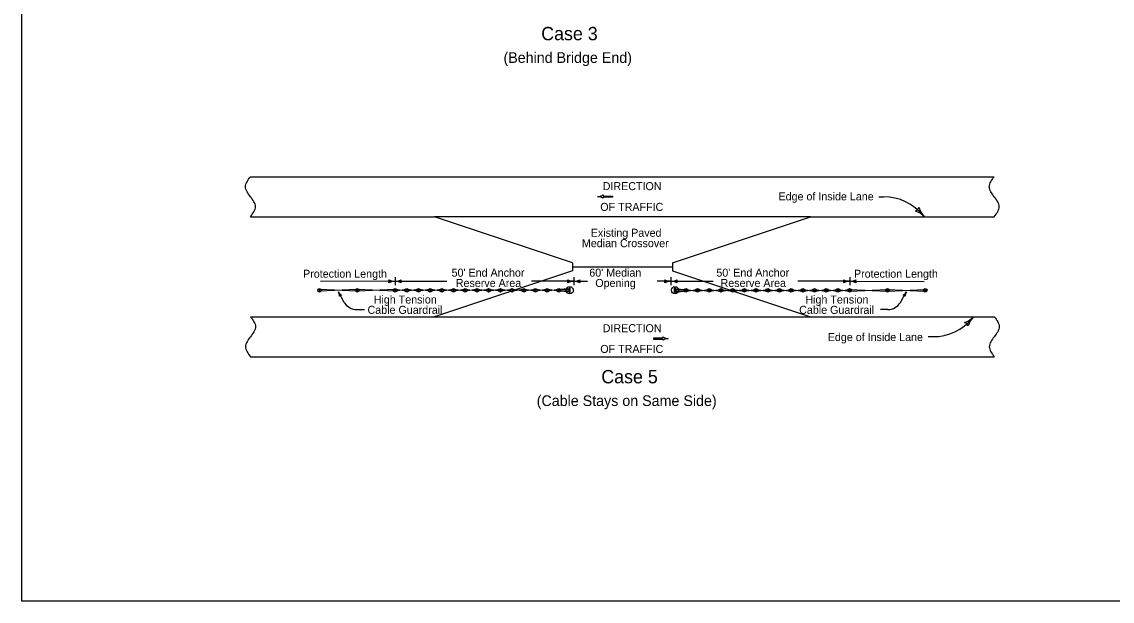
# Model space of a CAD drawing. Extents: x 10133 to 81668, y 7924 to 11018.
# Drawn here: x 20933 to 22568, y 7924 to 8793 of the extents above; entities that cross this region are included whole.
import ezdxf

# ---------------------------------------------------------------- set-up
doc = ezdxf.new("R2010")
doc.units = 0
for name, color, linetype in [('dsnCellElements', 7, 'Continuous'), ('DsnShtRevisedText', 7, 'Continuous'), ('dsnStdDimension', 7, 'Continuous'), ('Level 8', 7, 'Continuous'), ('SheetBorder', 7, 'Continuous')]:
    doc.layers.add(name, color=color, linetype=linetype)

msp = doc.modelspace()

# ---------------------------------------------------------------- linework, layer by layer
at = {"layer": 'dsnCellElements'}
for p, q in [((21758.3, 8425.6), (21908.3, 8425.6)), ((21435.2, 8391.3), (21379.4, 8389)), ((21435.2, 8389), (21379.4, 8391.3)), ((21491.9, 8391.3), (21436.1, 8389)), ((21491.9, 8389), (21436.1, 8391.3)), ((21509.5, 8391.3), (21492.8, 8389)), ((21509.5, 8389), (21492.8, 8391.3)), ((21527, 8391.3), (21510.4, 8389)), ((21527, 8389), (21510.4, 8391.3)), ((21544.6, 8391.3), (21527.9, 8389)), ((21544.6, 8389), (21527.9, 8391.3)), ((21562.1, 8391.3), (21545.5, 8389)), ((21562.1, 8389), (21545.5, 8391.3)), ((21579.6, 8391.3), (21563, 8389)), ((21579.6, 8389), (21563, 8391.3)), ((21597.2, 8391.3), (21580.6, 8389)), ((21597.2, 8389), (21580.6, 8391.3)), ((21614.7, 8391.3), (21598.1, 8389)), ((21614.7, 8389), (21598.1, 8391.3)), ((21632.3, 8389), (21615.7, 8391.3)), ((21632.3, 8391.3), (21615.7, 8389)), ((21649.8, 8391.3), (21633.2, 8389)), ((21649.8, 8389), (21633.2, 8391.3)), ((21667.3, 8391.3), (21650.8, 8389)), ((21667.3, 8389), (21650.8, 8391.3)), ((21684.9, 8391.3), (21668.3, 8389)), ((21684.9, 8389), (21668.3, 8391.3)), ((21702.4, 8391.3), (21685.9, 8389)), ((21702.4, 8389), (21685.9, 8391.3)), ((21720, 8391.3), (21703.4, 8389)), ((21720, 8389), (21703.4, 8391.3)), ((21737.5, 8391.3), (21721, 8389)), ((21737.5, 8389), (21721, 8391.3)), ((21754.3, 8392.5), (21737.5, 8391.3)), ((21754.3, 8391.3), (21738.5, 8391.3)), ((21912.3, 8392.5), (21929, 8391.3)), ((21912.3, 8391.3), (21928.1, 8391.3)), ((21929, 8391.3), (21945.6, 8389)), ((21929, 8389), (21945.6, 8391.3)), ((21946.5, 8391.3), (21963.2, 8389)), ((21946.5, 8389), (21963.2, 8391.3)), ((21964.1, 8391.3), (21980.7, 8389)), ((21964.1, 8389), (21980.7, 8391.3)), ((21981.6, 8391.3), (21998.3, 8389)), ((21981.6, 8389), (21998.3, 8391.3)), ((21999.2, 8391.3), (22015.8, 8389)), ((21999.2, 8389), (22015.8, 8391.3)), ((22016.7, 8391.3), (22033.4, 8389)), ((22016.7, 8389), (22033.4, 8391.3)), ((22034.3, 8389), (22050.9, 8391.3)), ((22034.3, 8391.3), (22050.9, 8389)), ((22051.8, 8391.3), (22068.5, 8389)), ((22051.8, 8389), (22068.5, 8391.3)), ((22069.4, 8391.3), (22086, 8389)), ((22069.4, 8389), (22086, 8391.3)), ((22086.9, 8391.3), (22103.6, 8389)), ((22086.9, 8389), (22103.6, 8391.3)), ((22104.5, 8391.3), (22121.1, 8389)), ((22104.5, 8389), (22121.1, 8391.3)), ((22122, 8391.3), (22138.6, 8389)), ((22122, 8389), (22138.6, 8391.3)), ((22139.6, 8391.3), (22156.2, 8389)), ((22139.6, 8389), (22156.2, 8391.3)), ((22157.1, 8391.3), (22173.7, 8389)), ((22157.1, 8389), (22173.7, 8391.3)), ((22174.7, 8391.3), (22230.4, 8389)), ((22174.7, 8389), (22230.4, 8391.3)), ((22231.4, 8391.3), (22287.1, 8389)), ((22231.4, 8389), (22287.1, 8391.3)), ((21754.3, 8387.8), (21737.5, 8389)), ((21754.3, 8389), (21738.5, 8389)), ((21912.3, 8389), (21928.1, 8389)), ((21912.3, 8387.8), (21929, 8389))]:
    msp.add_line(p, q, dxfattribs=at)
for points in [[(21379.4, 8389), (21379.4, 8391.3), (21378.5, 8391.3), (21378.5, 8389)], [(21436.1, 8389), (21436.1, 8391.3), (21435.2, 8391.3), (21435.2, 8389)], [(21436.1, 8389), (21436.1, 8391.3), (21435.2, 8391.3), (21435.2, 8389)], [(21492.8, 8389), (21492.8, 8391.3), (21491.9, 8391.3), (21491.9, 8389)], [(21492.8, 8389), (21492.8, 8391.3), (21491.9, 8391.3), (21491.9, 8389)], [(21510.4, 8389), (21510.4, 8391.3), (21509.5, 8391.3), (21509.5, 8389)], [(21527.9, 8389), (21527.9, 8391.3), (21527, 8391.3), (21527, 8389)], [(21545.5, 8389), (21545.5, 8391.3), (21544.6, 8391.3), (21544.6, 8389)], [(21563, 8389), (21563, 8391.3), (21562.1, 8391.3), (21562.1, 8389)], [(21580.6, 8389), (21580.6, 8391.3), (21579.6, 8391.3), (21579.6, 8389)], [(21598.1, 8389), (21598.1, 8391.3), (21597.2, 8391.3), (21597.2, 8389)], [(21615.7, 8389), (21615.7, 8391.3), (21614.7, 8391.3), (21614.7, 8389)], [(21633.2, 8389), (21633.2, 8391.3), (21632.3, 8391.3), (21632.3, 8389)], [(21650.8, 8389), (21650.8, 8391.3), (21649.8, 8391.3), (21649.8, 8389)], [(21668.3, 8389), (21668.3, 8391.3), (21667.3, 8391.3), (21667.3, 8389)], [(21685.9, 8389), (21685.9, 8391.3), (21684.9, 8391.3), (21684.9, 8389)], [(21703.4, 8389), (21703.4, 8391.3), (21702.4, 8391.3), (21702.4, 8389)], [(21721, 8389), (21721, 8391.3), (21720, 8391.3), (21720, 8389)], [(21738.5, 8389), (21738.5, 8391.3), (21737.5, 8391.3), (21737.5, 8389)], [(21754.9, 8387.1), (21754.9, 8393.2), (21753.7, 8393.2), (21753.7, 8387.1)], [(21911.7, 8387.1), (21911.7, 8393.2), (21912.9, 8393.2), (21912.9, 8387.1)], [(21928.1, 8389), (21928.1, 8391.3), (21929, 8391.3), (21929, 8389)], [(21945.6, 8389), (21945.6, 8391.3), (21946.5, 8391.3), (21946.5, 8389)], [(21963.2, 8389), (21963.2, 8391.3), (21964.1, 8391.3), (21964.1, 8389)], [(21980.7, 8389), (21980.7, 8391.3), (21981.6, 8391.3), (21981.6, 8389)], [(21998.3, 8389), (21998.3, 8391.3), (21999.2, 8391.3), (21999.2, 8389)], [(22015.8, 8389), (22015.8, 8391.3), (22016.7, 8391.3), (22016.7, 8389)], [(22033.4, 8389), (22033.4, 8391.3), (22034.3, 8391.3), (22034.3, 8389)], [(22050.9, 8389), (22050.9, 8391.3), (22051.8, 8391.3), (22051.8, 8389)], [(22068.5, 8389), (22068.5, 8391.3), (22069.4, 8391.3), (22069.4, 8389)], [(22086, 8389), (22086, 8391.3), (22086.9, 8391.3), (22086.9, 8389)], [(22103.6, 8389), (22103.6, 8391.3), (22104.5, 8391.3), (22104.5, 8389)], [(22121.1, 8389), (22121.1, 8391.3), (22122, 8391.3), (22122, 8389)], [(22138.6, 8389), (22138.6, 8391.3), (22139.6, 8391.3), (22139.6, 8389)], [(22156.2, 8389), (22156.2, 8391.3), (22157.1, 8391.3), (22157.1, 8389)], [(22173.7, 8389), (22173.7, 8391.3), (22174.7, 8391.3), (22174.7, 8389)], [(22173.7, 8389), (22173.7, 8391.3), (22174.7, 8391.3), (22174.7, 8389)], [(22230.4, 8389), (22230.4, 8391.3), (22231.4, 8391.3), (22231.4, 8389)], [(22230.4, 8389), (22230.4, 8391.3), (22231.4, 8391.3), (22231.4, 8389)], [(22287.1, 8389), (22287.1, 8391.3), (22288.1, 8391.3), (22288.1, 8389)]]:
    msp.add_lwpolyline(points, close=True, dxfattribs=at)
for centre, radius in [((21379, 8390.2), 2.66), ((21435.7, 8390.2), 2.66), ((21435.7, 8390.2), 2.66), ((21492.4, 8390.2), 2.66), ((21492.4, 8390.2), 2.66), ((21509.9, 8390.2), 2.66), ((21527.5, 8390.2), 2.66), ((21545, 8390.2), 2.66), ((21562.5, 8390.2), 2.66), ((21580.1, 8390.2), 2.66), ((21597.6, 8390.2), 2.66), ((21615.2, 8390.2), 2.66), ((21632.7, 8390.2), 2.66), ((21650.3, 8390.2), 2.66), ((21667.8, 8390.2), 2.66), ((21685.4, 8390.2), 2.66), ((21702.9, 8390.2), 2.66), ((21720.5, 8390.2), 2.66), ((21738, 8390.2), 2.66), ((21754.3, 8390.2), 5.4), ((21912.3, 8390.2), 5.4), ((21928.6, 8390.2), 2.66), ((21946.1, 8390.2), 2.66), ((21963.7, 8390.2), 2.66), ((21981.2, 8390.2), 2.66), ((21998.8, 8390.2), 2.66), ((22016.3, 8390.2), 2.66), ((22033.8, 8390.2), 2.66), ((22051.4, 8390.2), 2.66), ((22068.9, 8390.2), 2.66), ((22086.5, 8390.2), 2.66), ((22104, 8390.2), 2.66), ((22121.5, 8390.2), 2.66), ((22139.1, 8390.2), 2.66), ((22156.6, 8390.2), 2.66), ((22174.2, 8390.2), 2.66), ((22174.2, 8390.2), 2.66), ((22230.9, 8390.2), 2.66), ((22230.9, 8390.2), 2.66), ((22287.6, 8390.2), 2.66)]:
    msp.add_circle(centre, radius, dxfattribs=at)
at = {"layer": 'DsnShtRevisedText'}
for p, q in [((21796.2, 8530.8), (21796.2, 8530.8)), ((21804.3, 8533.3), (21804.3, 8531.5)), ((21804.3, 8531.5), (21818.3, 8531.5)), ((21818.3, 8530), (21804.3, 8530)), ((21804.3, 8530), (21804.3, 8528.2)), ((21818.3, 8531.5), (21818.3, 8530)), ((22218, 8530.4), (22225.4, 8530.4)), ((21492.3, 8409.7), (21492.3, 8397.7)), ((21760.4, 8409.7), (21760.4, 8397.7)), ((21906.2, 8409.7), (21906.2, 8397.7)), ((22174.3, 8409.7), (22174.3, 8397.7)), ((21492.3, 8403.7), (21380.3, 8403.2)), ((21492.3, 8403.7), (21570.2, 8403.7)), ((21760.4, 8403.7), (21697, 8403.7)), ((21760.4, 8403.7), (21781.1, 8404)), ((21906.2, 8403.7), (21885.4, 8404)), ((21906.2, 8403.7), (21969.5, 8403.7)), ((22174.3, 8403.7), (22096.4, 8403.7)), ((22174.3, 8403.7), (22286.2, 8403.2)), ((21416.2, 8372.1), (21407.3, 8387.8)), ((22250.3, 8372.1), (22259.2, 8387.8)), ((21435, 8361.3), (21446.3, 8361.3)), ((22231.5, 8361.3), (22220.3, 8361.3)), ((21894.2, 8318.5), (21880.2, 8318.5)), ((21880.2, 8318.5), (21880.2, 8317)), ((21880.2, 8317), (21894.2, 8317)), ((21894.2, 8320.3), (21894.2, 8318.5)), ((21894.2, 8317), (21894.2, 8315.2)), ((21902.3, 8317.7), (21902.3, 8317.7)), ((22291.9, 8320.7), (22299.3, 8320.7))]:
    msp.add_line(p, q, dxfattribs=at)
for centre, radius, start, end in [((21795.5, 8547.1), 16.4, 272.352, 302.382), ((21795.5, 8514.4), 16.4, 57.618, 87.648), ((22225.4, 8454.2), 76.2, 39.0106, 90), ((22267.4, 8520.4), 12.5, 295.2639, 330.7306), ((22262.3, 8478.5), 32.4, 42.9973, 71.0698), ((22309.6, 8522.7), 32.4, 194.9248, 222.9973), ((21476.2, 8403.7), 7.39, 342.2666, 17.7333), ((21492.3, 8422.8), 19.1, 241.9275, 270), ((21492.3, 8384.6), 19.1, 90, 118.0725), ((21492.3, 8422.8), 19.1, 270, 298.0725), ((21492.3, 8384.6), 19.1, 61.9275, 90), ((21508.3, 8403.7), 7.39, 162.2666, 197.7334), ((21744.3, 8403.7), 7.39, 342.2667, 17.7334), ((21760.4, 8422.8), 19.1, 241.9275, 270), ((21760.4, 8384.6), 19.1, 90, 118.0725), ((21760.4, 8422.8), 19.1, 270, 298.0725), ((21760.4, 8384.6), 19.1, 61.9275, 90), ((21776.4, 8403.7), 7.39, 162.2666, 197.7334), ((21890.2, 8403.7), 7.39, 342.2667, 17.7334), ((21906.2, 8422.8), 19.1, 241.9275, 270), ((21906.2, 8384.6), 19.1, 90, 118.0725), ((21906.2, 8422.8), 19.1, 270, 298.0725), ((21906.2, 8384.6), 19.1, 61.9275, 90), ((21922.2, 8403.7), 7.39, 162.2666, 197.7334), ((22158.3, 8403.7), 7.39, 342.2667, 17.7334), ((22174.3, 8422.8), 19.1, 241.9275, 270), ((22174.3, 8384.6), 19.1, 90, 118.0725), ((22174.3, 8422.8), 19.1, 270, 298.0725), ((22174.3, 8384.6), 19.1, 61.9275, 90), ((22190.3, 8403.7), 7.39, 162.2666, 197.7334), ((21395.6, 8380.9), 13.6, 2.1589, 30.2314), ((21419.1, 8394.6), 13.6, 210.2314, 238.3038), ((21413.1, 8377.9), 5.25, 102.498, 137.9647), ((22247.5, 8394.6), 13.6, 301.6962, 329.7686), ((22253.5, 8377.9), 5.25, 42.0353, 77.502), ((22271, 8380.9), 13.6, 149.7686, 177.8411), ((21435, 8383.1), 21.8, 210.2243, 270), ((22231.5, 8383.1), 21.8, 270, 329.7757), ((22299.3, 8396.9), 76.2, 270, 320.9894), ((22336.2, 8372.7), 32.4, 288.9302, 317.0027), ((22341.3, 8330.7), 12.5, 29.2694, 64.7361), ((22383.5, 8328.5), 32.4, 137.0027, 165.0752), ((21902.9, 8334.1), 16.4, 237.618, 267.648), ((21902.9, 8301.4), 16.4, 92.352, 122.382)]:
    msp.add_arc(centre, radius, start, end, dxfattribs=at)
at = {"layer": 'dsnStdDimension'}
for p, q in [((21275.5, 8560.6), (22391.1, 8560.6)), ((21275.5, 8500.6), (21551.3, 8500.6)), ((21758.3, 8431.6), (21551.3, 8500.6)), ((22115.3, 8500.6), (21551.3, 8500.6)), ((21908.3, 8431.6), (22115.3, 8500.6)), ((22112.2, 8500.6), (22391.1, 8500.6)), ((21758.3, 8431.6), (21758.3, 8419.6)), ((21908.3, 8431.6), (21908.3, 8419.6)), ((21758.3, 8419.6), (21551.3, 8350.6)), ((21908.3, 8419.6), (22115.3, 8350.6)), ((21275.5, 8350.6), (21554.4, 8350.6)), ((21554.4, 8350.6), (22115.3, 8350.6)), ((22115.3, 8350.6), (22391.1, 8350.6)), ((21275.5, 8290.6), (22391.1, 8290.6))]:
    msp.add_line(p, q, dxfattribs=at)
for points in [[(21275.5, 8500.6), (21283, 8515.6), (21275.5, 8530.6), (21268, 8545.6), (21275.5, 8560.6)], [(22391.1, 8500.6), (22398.6, 8515.6), (22391.1, 8530.6), (22383.6, 8545.6), (22391.1, 8560.6)], [(21275.5, 8350.6), (21283, 8335.6), (21275.5, 8320.6), (21268, 8305.6), (21275.5, 8290.6)], [(22391.1, 8350.6), (22398.6, 8335.6), (22391.1, 8320.6), (22383.6, 8305.6), (22391.1, 8290.6)]]:
    msp.add_spline(points, degree=3, dxfattribs=at)
at = {"layer": 'SheetBorder'}
msp.add_lwpolyline([(20932.5, 9944), (24067.5, 9944), (24067.5, 7924), (20932.5, 7924)], close=True, dxfattribs=at)

# ---------------------------------------------------------------- texts
at = {"layer": 'DsnShtRevisedText'}
for s, p in [('DIRECTION', (21803.8, 8540.4)), ('Edge of Inside Lane', (22067.5, 8525.1)), ('OF TRAFFIC', (21800.2, 8509.3)), ('Existing Paved', (21785.9, 8470.5)), ('Median Crossover', (21772.6, 8454.9)), ("50' End Anchor", (21577.2, 8410.7)), ("60' Median", (21783.7, 8410.7)), ("50' End Anchor", (21974.3, 8410.7)), ('Protection Length', (21354.4, 8409.1)), ('Reserve Area', (21583.5, 8395.2)), ('Opening', (21792.7, 8395.2)), ('Reserve Area', (21980.6, 8395.2)), ('Protection Length', (22180.7, 8409.1)), ('High Tension', (21460.4, 8370.4)), ('High Tension', (22107.8, 8370.4)), ('Cable Guardrail', (21451.1, 8354.9)), ('Cable Guardrail', (22098.5, 8354.9)), ('DIRECTION', (21803.8, 8327.4)), ('Edge of Inside Lane', (22141.4, 8314.1)), ('OF TRAFFIC', (21800.2, 8296.3))]:
    msp.add_text(s, height=12, dxfattribs=at).set_placement(p)
at = {"layer": 'Level 8'}
for s, height, p in [('Case 3', 20, (21711.6, 8765.2)), ('(Behind Bridge End)', 16, (21655, 8731.2)), ('Case 5', 20, (21801.7, 8250.7)), ('(Cable Stays on Same Side)', 16, (21704.8, 8216.7))]:
    msp.add_text(s, height=height, dxfattribs=at).set_placement(p)

doc.saveas('drawing.dxf')
